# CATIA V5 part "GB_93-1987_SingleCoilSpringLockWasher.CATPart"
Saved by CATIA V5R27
Part number: GB 93-1987 标准型弹簧垫圈
Bounding box of the stored display mesh (mm): x -7.7 to 7.7, y -7.69 to 7.699, z 0 to 2.6
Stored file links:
  E:\资料\Catia超级副本\GB 93-1987 标准型弹簧垫圈\GB_93-1987_SingleCoilSpringLockWasher.CATPart
  E:\资料\Catia超级副本\GB 93-1987 标准型弹簧垫圈\GB93-87_SingleCoilSpringLockWasher_DesignTable.xlsx
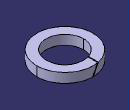
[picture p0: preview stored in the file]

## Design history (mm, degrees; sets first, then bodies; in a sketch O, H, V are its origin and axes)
Parameters
  b = 2.6 mm {design table}
  d = 10.2 mm {design table}
  `公称直径` = 10 mm {design table}
AxisSystem1: origin (0, 0, 0), X (1, 0, 0), Y (0, 1, 0), Z (0, 0, 1)
Set1 "Inputs"
  Plane1: type Normal, Curve Line1, RefPoint Point1, Ratio 0
  Point1: (0, 0, 0), in AxisSystem1
Body1 (main body)
  Set2
    Line1: type PtDir, RefPoint Point1, Direction (0, 0, 1), Start 0, End 20
    Sketch1 on Plane1, origin (0, 0, 0), H (1, 0, 0), V (0, 1, 0)
      circle A1 centre (0, 0) radius 7.7
      circle A2 centre (0, 0) radius 5.1
      radius A1 = 7.7 {= d /2+b}
      radius A2 = 5.1 {= d /2}
      concentricity: A2 A1
    Line2: type PtDir, RefPoint Point1, Direction (1, 0, 0), Start 0, End 20
    Plane2: type 2Lines, Element1 Line2, Element2 Line1
  Pad1: profile Sketch1, direction (0, 0, 1), length 2.6 {= b}
  Sketch2 on Plane2, origin (0, 0, 0), H (1, 0, 0), V (0, 0, 1)
    line L1 (4.9134, -8.7103) -> (5.0866, -8.6103)
    line L2 (5.0866, -8.6103) -> (-4.9134, 8.7103)
    line L3 (-4.9134, 8.7103) -> (-5.0866, 8.6103)
    line L4 (-5.0866, 8.6103) -> (4.9134, -8.7103)
    reference projected point E1 (0, 0) from Point1
    reference projected point E2 (0, 0) from Point1
    distance L2 L4 = 0.2
    distance L4 E1 = 0.1 {= Sketch2.distance(L2 L4) /2}
    angle L4 V = 150
    length L4 = 20
    distance L1 E2 = 10
    parallelism: L1 L3
    perpendicularity: L1 L2
  Pocket1: profile Sketch2, direction (0, 1, 0), through (limit type 3)
Relations
  design table, configuration 8, drives b, d, `公称直径`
